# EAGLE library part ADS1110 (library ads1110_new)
Analog/Digital conventer i2c Bus max: 2.048v
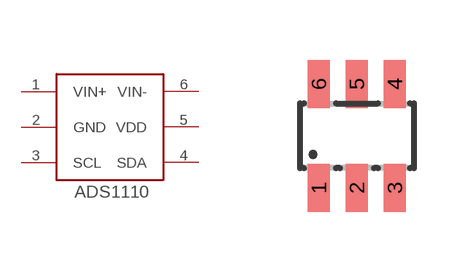
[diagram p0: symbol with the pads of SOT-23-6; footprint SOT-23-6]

Designator prefix IC

## ADS1110  [SOT-23-6]
1  VIN+
2  GND
3  SCL
4  SDA
5  VDD
6  VIN-

## Footprint SOT-23-6 (pad centres in mm)
Small Outline SOT-23-6 Created by Slawomir Grzegorzek tygrysek@vidmo.net
smd 0.55 x 1.2: 1 -0.95,-1.3; 2 0,-1.3; 3 0.95,-1.3; 4 0.95,1.3; 5 0,1.3; 6 -0.95,1.3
